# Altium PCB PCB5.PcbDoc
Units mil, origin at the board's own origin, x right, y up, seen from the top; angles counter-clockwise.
Board outline 6000 x 4000 mil, 2 copper layers (Top Layer, Bottom Layer); 73 components, 49 nets, 211 pads, 62 vias.
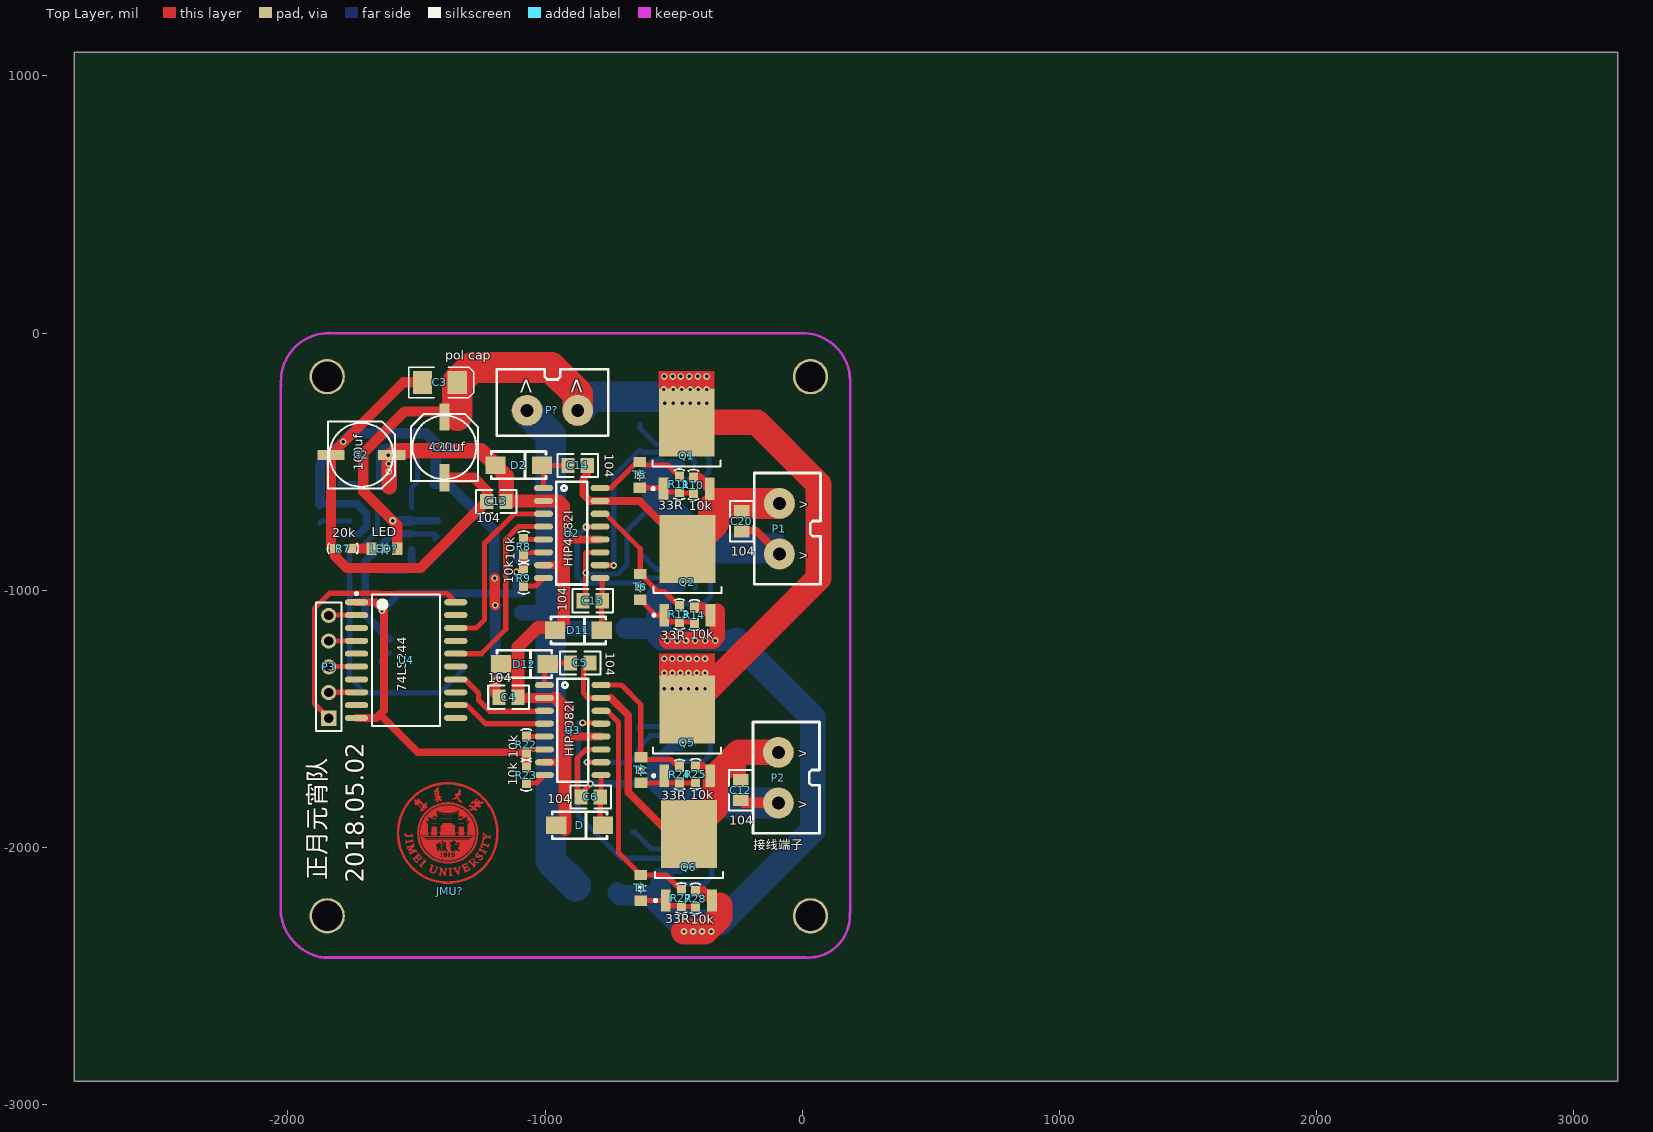
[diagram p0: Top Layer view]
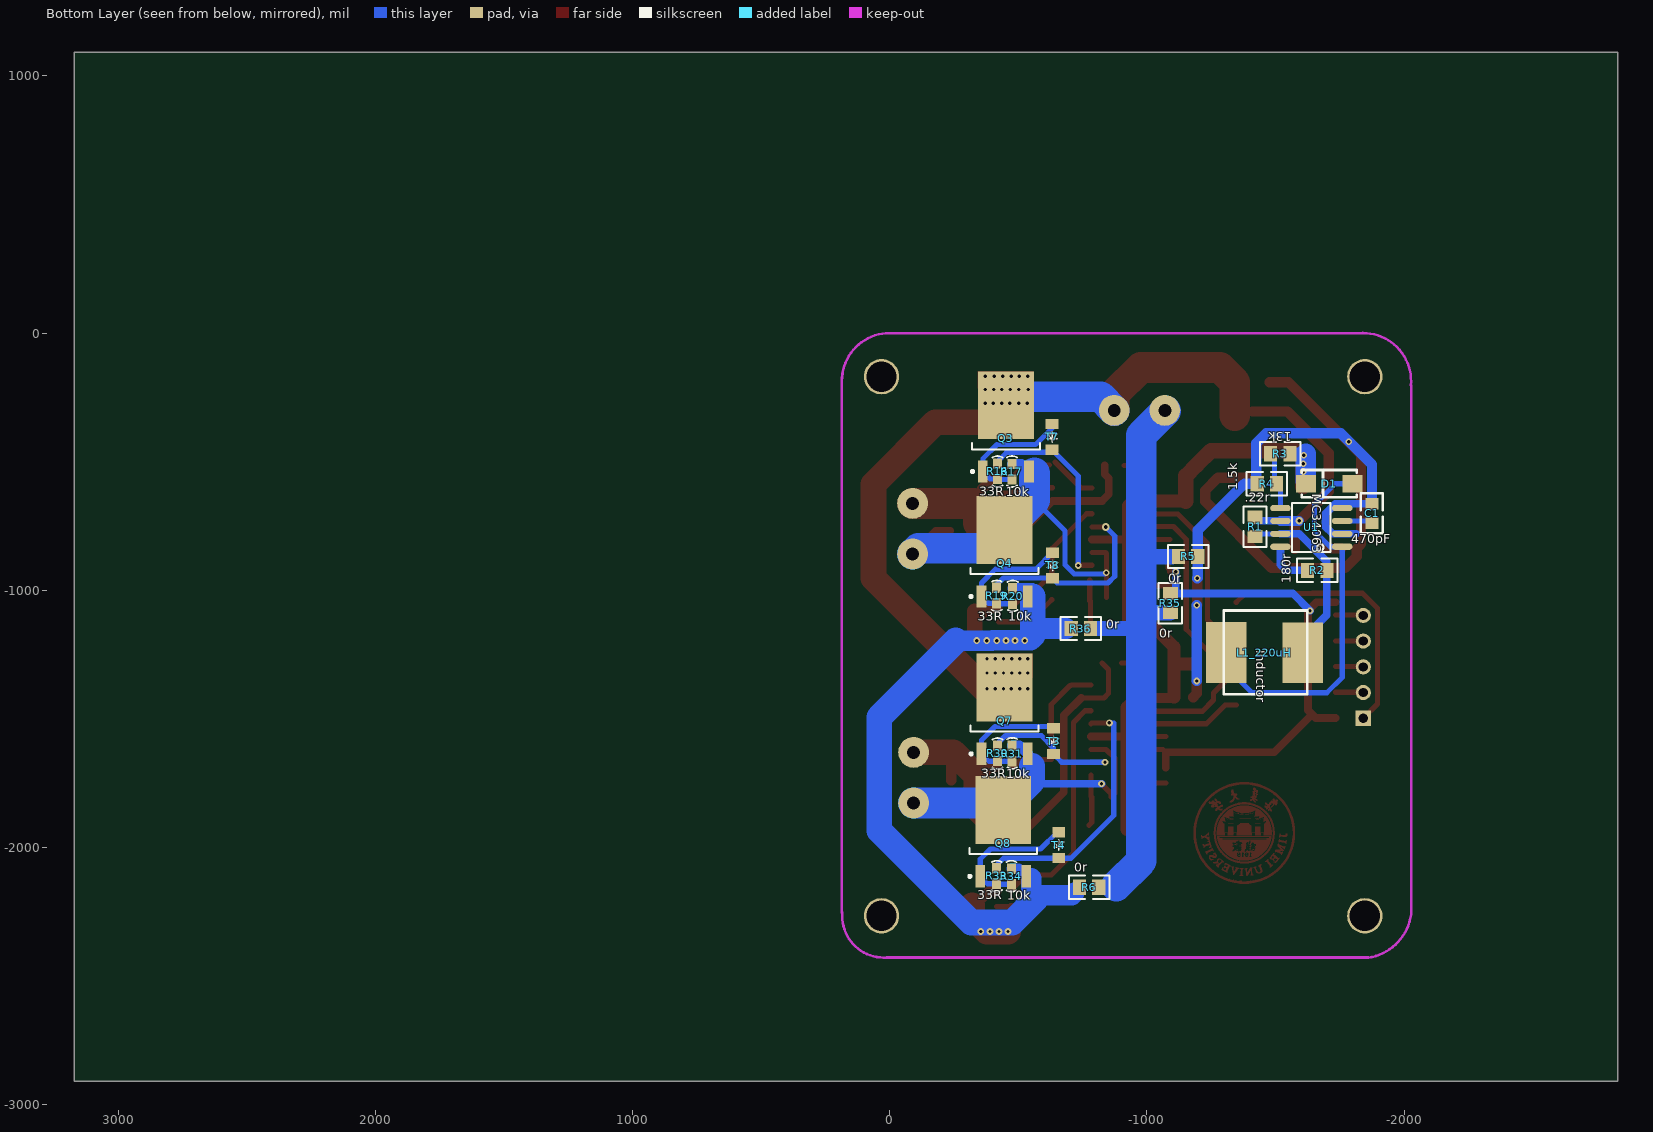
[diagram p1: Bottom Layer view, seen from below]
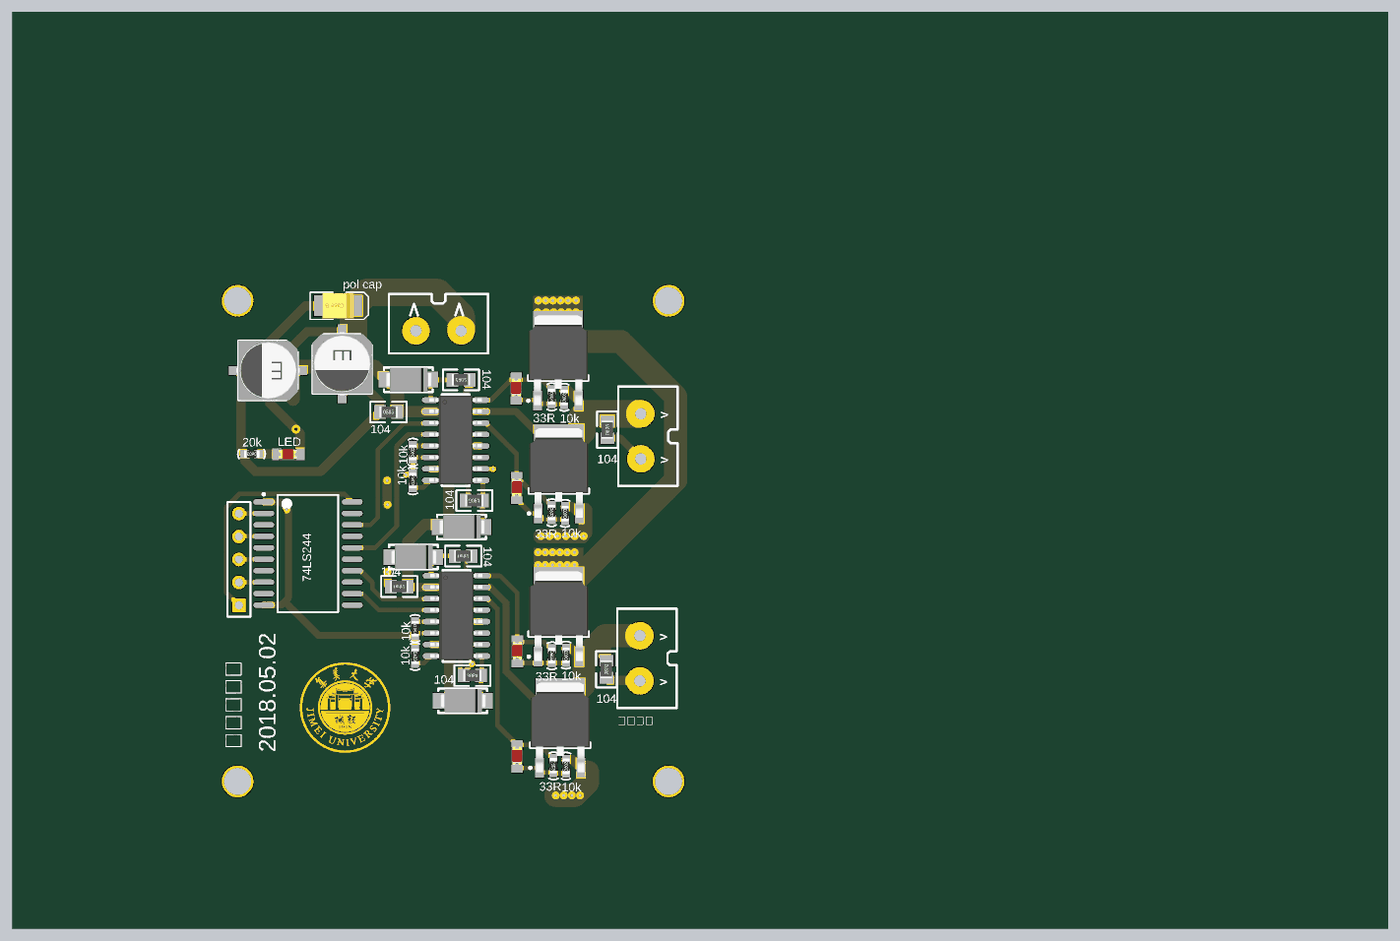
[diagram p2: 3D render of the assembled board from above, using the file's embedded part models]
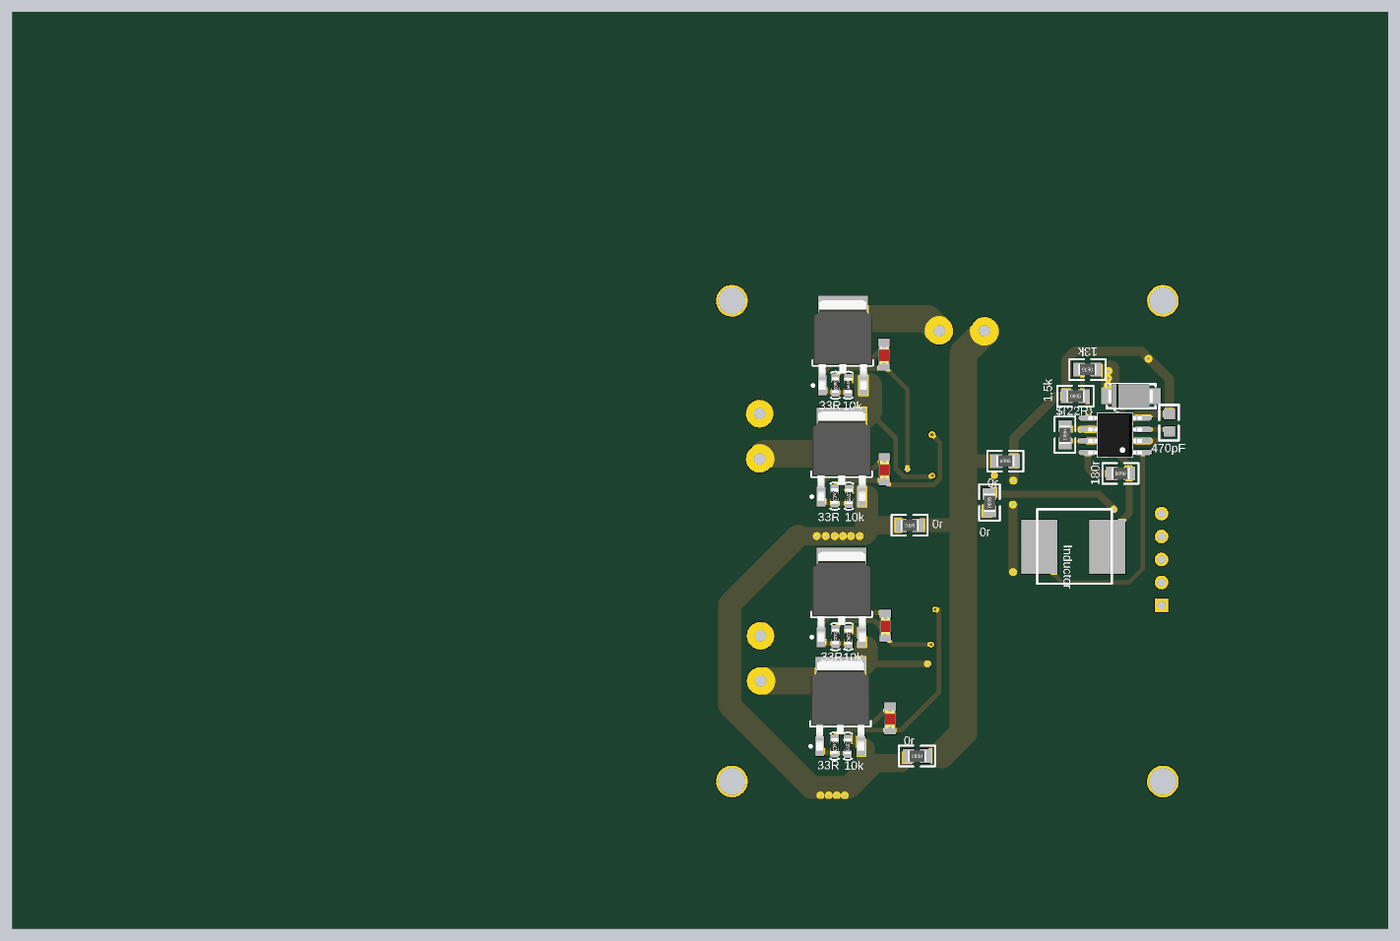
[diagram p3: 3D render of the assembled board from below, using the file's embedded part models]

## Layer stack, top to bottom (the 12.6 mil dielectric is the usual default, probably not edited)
Top Solder: solder mask 0.4, Solder Resist, Dk 3.5
Top Layer: signal copper 1.4
Dielectric 1: dielectric 12.6, FR-4, Dk 4.8
Bottom Layer: signal copper 1.4
Bottom Solder: solder mask 0.4, Solder Resist, Dk 3.5

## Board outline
-2830,-2908 3170,-2908 3170,1092 -2830,1092

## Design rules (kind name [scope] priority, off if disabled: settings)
Clearance [All] p1: gap=10
PolygonConnect [All] p1: connectstyle=Relief reliefconductorwidth=10 reliefentries=4 polygonreliefangle="90 Angle" airgapwidth=10
RoutingVias [All] p1: holewidth=28 width=50 viastyle="Through Hole" minholewidth=28 minwidth=50 maxholewidth=28 maxwidth=50
SolderMaskExpansion [All] p1: expansion=4
Width [All] p1: maxlimit=150 minlimit=10 preferedwidth=20 minimp=50.000000 maximp=50.000000 favimp=50.000000
30 further rules are at their usual default settings.

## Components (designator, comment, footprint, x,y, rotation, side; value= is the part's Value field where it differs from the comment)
C1 "470pF" 0805#1 -1875,-738 r90 bottom
C2 "100uf" ED6.3 -1714,-473 r180 top
C3 "pol cap" "pol cap(10uF)" -1529,-121 r0 top
C4 "104" 0805#2 -1142,-1410 r0 top
C5 "104" 0805#2 -863,-1277 r0 top
C6 "104" 0805#2 -823,-1808 r180 top
C11 "470uf" ED6.3 -1391,-444 r270 top
C12 "104" 0805#2 -244,-1776 r90 top
C13 "104" 0805#2 -1189,-649 r0 top
C14 "104" 0805#2 -873,-509 r0 top
C15 "104" 0805#2 -815,-1045 r180 top
C20 "104" 0805#2 -240,-731 r90 top
D "二极管" 二极管 -861,-1913 r0 top
D1 "二极管" 二极管 -1704,-585 r0 bottom
D2 "D" 二极管 -1098,-513 r0 top
D11 "二极管" 二极管 -866,-1155 r0 top
D12 "二极管" 二极管 -1076,-1286 r0 top
JMU? "LOGO(JMU)" JMU_logo（1） -1369,-2170 r0 top
L1_220uH "Inductor" 电感8*8 -1605,-1242 r270 bottom
LED? "LED" LED(0805) -1625,-838 r180 top
P1 "接线端子" 接线端子 -194,-980 r90 top
P2 "接线端子" 接线端子 -198,-1948 r90 top
P3 "Header 5" HDR1X5 -1841,-1497 r90 top
P? "电源接线端子" 接线端子 -751,-405 r180 top
Q1 "IR7843" "TO-252  mos管" -449.49,-431.19 r90 top
Q2 "IR7843" "TO-252  mos管" -446.49,-923.19 r90 top
Q3 "IR7843" "TO-252  mos管" -451.76,-364.77 r90 bottom
Q4 "IR7843" "TO-252  mos管" -446.49,-850.19 r90 bottom
Q5 "IR7843" "TO-252  mos管" -447.49,-1547.19 r90 top
Q6 "IR7843" "TO-252  mos管" -440.49,-2032.19 r90 top
Q7 "IR7843" "TO-252  mos管" -446.49,-1462.19 r90 bottom
Q8 "IR7843" "TO-252  mos管" -441.49,-1938.19 r90 bottom
R1 ".22r" 0805#2 -1425,-753 r270 bottom
R2 "180r" 0805#2 -1662,-927 r0 bottom
R3 "13k" 0805#2 -1518,-474 r0 bottom
R4 "1.5k" 0805#2 -1466,-580 r180 bottom
R5 "0r" 0805#2 -1160,-863 r180 bottom
R6 "0r" 0805#2 -775,-2159 r0 bottom
R7 "20k" 0603 -1780,-837 r180 top
R8 "10k" 0603 -1083,-835 r90 top
R9 "10k" 0603 -1083,-948 r270 top
R10 "10k" 0603 -423,-596 r90 top
R11 "33R" 0603 -478,-582 r270 top
R13 "33R" 0603 -478,-1087 r270 top
R14 "10k" 0603 -419,-1102 r90 top
R16 "33R" 0603 -419.28,-531.58 r270 bottom
R17 "10k" 0603 -475.28,-543.58 r90 bottom
R19 "33R" 0603 -416,-1015 r270 bottom
R20 "10k" 0603 -478,-1027 r90 bottom
R22 "10k" 0603 -1073,-1604 r90 top
R23 "10k" 0603 -1073,-1714 r270 top
R24 "33R" 0603 -477,-1711 r270 top
R25 "10k" 0603 -415,-1720 r90 top
R27 "33R" 0603 -470,-2191 r270 top
R28 "10k" 0603 -415,-2204 r90 top
R30 "33R" 0603 -419,-1628 r270 bottom
R31 "10k" 0603 -476,-1639 r90 bottom
R33 "33R" 0603 -416,-2105 r270 bottom
R34 "10k" 0603 -473,-2117 r90 bottom
R35 "0r" 0805#2 -1086,-1049 r90 bottom
R36 "0r" 0805#2 -743,-1153 r0 bottom
T1 "二极管" LED(0805) -628,-2156 r90 top
T2 "二极管" LED(0805) -627,-1698 r90 top
T3 "二极管" LED(0805) -637,-1586 r270 bottom
T4 "二极管" LED(0805) -657,-1990 r270 bottom
T5 "二极管" LED(0805) -632,-551 r90 top
T6 "二极管" LED(0805) -630,-986 r90 top
T7 "二极管" LED(0805) -631,-403 r270 bottom
T8 "二极管" LED(0805) -633,-903 r270 bottom
U1 "MC34063" SO8NB -1639,-755 r90 bottom
U2 "HIP4082I" HIP4082I -896,-762 r0 top
U3 "HIP4082I" HIP4082I -892.47,-1528 r0 top
U4 "74LS244" 74LS244D -1540,-1271 r0 top

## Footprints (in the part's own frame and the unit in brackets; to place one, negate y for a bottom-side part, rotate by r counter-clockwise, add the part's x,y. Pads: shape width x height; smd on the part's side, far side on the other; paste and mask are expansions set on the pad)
74LS244D [mm] "SOP-20"
  oval 2.3x0.6 smd: 1(-4.9,5.715) 2(-4.9,4.445) 3(-4.9,3.175) 4(-4.9,1.905) 5(-4.9,0.635) 6(-4.9,-0.635) 7(-4.9,-1.905) 8(-4.9,-3.175) 9(-4.9,-4.445) 10(-4.9,-5.715) 11(4.9,-5.715) 12(4.9,-4.445) 13(4.9,-3.175) 14(4.9,-1.905) 15(4.9,-0.635) 16(4.9,0.635) 17(4.9,1.905) 18(4.9,3.175) 19(4.9,4.445) 20(4.9,5.715)
  silkscreen extent -5.02,-6.5 3.35,6.69, body extent -3.8,-6.5 3.8,6.5, height 2.65
0603 [mil]
  rect 40x35 smd: 1(-25,0) 2(35,0)
  silkscreen extent -54,-20 66,20, body extent -28,-16 38,16, height 22
0805#1 [mil]
  rect 45x50 smd: 1(0,0) 2(75,0)
  silkscreen extent -40,-41 115,44
0805#2 [mil]
  rect 51.18x59.06 smd: 1(-37.4,-5) 2(37.4,-5)
  silkscreen extent -79,-50 79,40, body extent -39,-30 39,20, height 22
ED6.3 [mm]
  rect 2.7x1 smd: 1(-3,0) 2(3,0)
  silkscreen extent -3.3,-3.3 3.3,3.3, body extent -3.5,-3.3 3.5,3.3, height 5.2
HDR1X5 [mm] "Connector; Header; 5 Position"
  rect 1.5x1.5 hole 0.9: 1(0,0)
  round 1.5 hole 0.9: 2(2.54,0) 3(5.08,0) 4(7.62,0) 5(10.16,0)
  silkscreen extent -1.27,-1.27 11.43,1.27
HIP4082I [mil]
  oval 74x24 smd: 1(-110,160) 2(-110,110) 3(-110,60) 4(-110,10) 5(-110,-40) 6(-110,-90) 7(-110,-140) 8(-110,-190) 9(110,-190) 10(110,-140) 11(110,-90) 12(110,-40) 13(110,10) 14(110,60) 15(110,110) 16(110,160)
  silkscreen extent -60,-215 60,185, body extent -115,-207 113,179, height 69
JMU_logo（1） [mil]
  Top Layer region: 8.21,175.64 7.21,175.64 7.21,176.64 8.21,176.64
  Top Layer region: 27.21,181.64 26.21,181.64 26.21,180.64 24.21,180.64 24.21,183.64 27.21,183.64
  Top Layer region: -42.79,162.64 -43.79,162.64 -43.79,161.64 -46.79,161.64 -46.79,163.64 -44.79,163.64 -44.79,164.64 -42.79,164.64
  Top Layer region: -32.79,175.64 -31.79,175.64 -31.79,174.64 -30.79,174.64 -30.79,173.64 -31.79,173.64 -31.79,172.64 -32.79,172.64 -32.79,171.64 -33.79,171.64 -33.79,176.64 -32.79,176.64
  Top Layer region: -29.79,165.64 -30.79,165.64 -30.79,164.64 -31.79,164.64 -31.79,163.64 -33.79,163.64 -33.79,164.64 -34.79,164.64 -34.79,166.64 -31.79,166.64 -31.79,167.64 -29.79,167.64
  Top Layer region: -103.79,318.64 -101.79,318.64 -101.79,313.64 -102.79,313.64 -102.79,312.64 -104.79,312.64 -104.79,313.64 -105.79,313.64 -105.79,314.64 -106.79,314.64 -106.79,319.64 -103.79,319.64
  Top Layer region: -89.79,330.64 -88.79,330.64 -88.79,329.64 -89.79,329.64 -89.79,327.64 -90.79,327.64 -90.79,326.64 -92.79,326.64 -92.79,325.64 -93.79,325.64 -93.79,324.64 -95.79,324.64 -95.79,325.64 -94.79,325.64 -94.79,327.64 -95.79,327.64 -95.79,326.64 -97.79,326.64 -97.79,328.64 -96.79,328.64 -96.79,329.64 -95.79,329.64 -95.79,330.64 -94.79,330.64 -94.79,331.64 -92.79,331.64 -92.79,332.64 -89.79,332.64
  Top Layer region: -40.79,358.64 -37.79,358.64 -37.79,357.64 -34.79,357.64 -34.79,356.64 -32.79,356.64 -32.79,355.64 -31.79,355.64 -31.79,352.64 -32.79,352.64 -32.79,351.64 -36.79,351.64 -36.79,352.64 -37.79,352.64 -37.79,354.64 -39.79,354.64 -39.79,355.64 -41.79,355.64 -41.79,356.64 -42.79,356.64 -42.79,358.64 -41.79,358.64 -41.79,359.64 -40.79,359.64
  Top Layer region: 105.21,357.64 106.21,357.64 106.21,355.64 105.21,355.64 105.21,354.64 104.21,354.64 104.21,353.64 103.21,353.64 103.21,351.64 102.21,351.64 102.21,350.64 101.21,350.64 101.21,349.64 99.21,349.64 99.21,348.64 97.21,348.64 97.21,349.64 96.21,349.64 96.21,352.64 97.21,352.64 97.21,354.64 98.21,354.64 98.21,355.64 99.21,355.64 99.21,356.64 100.21,356.64 100.21,357.64 101.21,357.64 101.21,359.64 105.21,359.64
  Top Layer region: 7.21,87.64 4.21,87.64 4.21,86.64 3.21,86.64 3.21,78.64 4.21,78.64 4.21,64.64 5.21,64.64 5.21,62.64 9.21,62.64 9.21,61.64 8.21,61.64 8.21,60.64 -4.79,60.64 -4.79,61.64 -3.79,61.64 -3.79,62.64 -0.79,62.64 -0.79,72.64 -1.79,72.64 -1.79,86.64 -3.79,86.64 -3.79,87.64 -5.79,87.64 -5.79,89.64 7.21,89.64
  Top Layer region: -100.79,123.64 -99.79,123.64 -99.79,122.64 -98.79,122.64 -98.79,121.64 -97.79,121.64 -97.79,120.64 -96.79,120.64 -96.79,119.64 -94.79,119.64 -94.79,118.64 -93.79,118.64 -93.79,117.64 -92.79,117.64 -92.79,116.64 -91.79,116.64 -91.79,114.64 -93.79,114.64 -93.79,115.64 -96.79,115.64 -96.79,114.64 -97.79,114.64 -97.79,113.64 -98.79,113.64 -98.79,112.64 -99.79,112.64 -99.79,111.64 -100.79,111.64 -100.79,109.64 -101.79,109.64 -101.79,108.64 -102.79,108.64 -102.79,107.64 -103.79,107.64 -103.79,106.64 -104.79,106.64 -104.79,105.64 -105.79,105.64 -105.79,103.64 -106.79,103.64 -106.79,102.64 -107.79,102.64 -107.79,101.64 -108.79,101.64 -108.79,100.64 -109.79,100.64 -109.79,98.64 -110.79,98.64 -110.79,96.64 -109.79,96.64 -109.79,95.64 -108.79,95.64 -108.79,94.64 -109.79,94.64 -109.79,93.64 -110.79,93.64 -110.79,94.64 -111.79,94.64 -111.79,95.64 -112.79,95.64 -112.79,96.64 -113.79,96.64 -113.79,97.64 -115.79,97.64 -115.79,98.64 -116.79,98.64 -116.79,99.64 -117.79,99.64 -117.79,100.64 -118.79,100.64 -118.79,101.64 -119.79,101.64 -119.79,102.64 -116.79,102.64 -116.79,101.64 -114.79,101.64 -114.79,102.64 -113.79,102.64 -113.79,103.64 -112.79,103.64 -112.79,104.64 -111.79,104.64 -111.79,106.64 -110.79,106.64 -110.79,107.64 -109.79,107.64 -109.79,108.64 -108.79,108.64 -108.79,109.64 -107.79,109.64 -107.79,111.64 -106.79,111.64 -106.79,112.64 -105.79,112.64 -105.79,113.64 -104.79,113.64 -104.79,114.64 -103.79,114.64 -103.79,115.64 -102.79,115.64 -102.79,117.64 -101.79,117.64 -101.79,118.64 -100.79,118.64 -100.79,121.64 -101.79,121.64 -101.79,122.64 -102.79,122.64 -102.79,123.64 -101.79,123.64 -101.79,124.64 -100.79,124.64
  Top Layer region: -144.79,199.64 -143.79,199.64 -143.79,194.64 -142.79,194.64 -142.79,190.64 -144.79,190.64 -144.79,192.64 -145.79,192.64 -145.79,193.64 -150.79,193.64 -150.79,192.64 -155.79,192.64 -155.79,191.64 -160.79,191.64 -160.79,190.64 -165.79,190.64 -165.79,189.64 -168.79,189.64 -168.79,188.64 -169.79,188.64 -169.79,184.64 -170.79,184.64 -170.79,185.64 -171.79,185.64 -171.79,190.64 -172.79,190.64 -172.79,195.64 -173.79,195.64 -173.79,197.64 -172.79,197.64 -172.79,198.64 -171.79,198.64 -171.79,196.64 -170.79,196.64 -170.79,195.64 -169.79,195.64 -169.79,194.64 -168.79,194.64 -168.79,195.64 -162.79,195.64 -162.79,196.64 -158.79,196.64 -158.79,197.64 -152.79,197.64 -152.79,198.64 -148.79,198.64 -148.79,199.64 -146.79,199.64 -146.79,203.64 -144.79,203.64
  Top Layer region: 117.21,168.64 118.21,168.64 118.21,167.64 117.21,167.64 117.21,164.64 118.21,164.64 118.21,163.64 120.21,163.64 120.21,162.64 122.21,162.64 122.21,161.64 124.21,161.64 124.21,160.64 126.21,160.64 126.21,159.64 128.21,159.64 128.21,158.64 130.21,158.64 130.21,157.64 132.21,157.64 132.21,156.64 134.21,156.64 134.21,155.64 136.21,155.64 136.21,154.64 139.21,154.64 139.21,155.64 140.21,155.64 140.21,156.64 142.21,156.64 142.21,155.64 141.21,155.64 141.21,153.64 140.21,153.64 140.21,150.64 139.21,150.64 139.21,148.64 138.21,148.64 138.21,146.64 137.21,146.64 137.21,144.64 135.21,144.64 135.21,149.64 134.21,149.64 134.21,150.64 132.21,150.64 132.21,151.64 129.21,151.64 129.21,152.64 128.21,152.64 128.21,153.64 126.21,153.64 126.21,154.64 124.21,154.64 124.21,155.64 122.21,155.64 122.21,156.64 120.21,156.64 120.21,157.64 118.21,157.64 118.21,158.64 116.21,158.64 116.21,159.64 114.21,159.64 114.21,158.64 113.21,158.64 113.21,157.64 112.21,157.64 112.21,156.64 111.21,156.64 111.21,157.64 110.21,157.64 110.21,158.64 111.21,158.64 111.21,160.64 112.21,160.64 112.21,162.64 113.21,162.64 113.21,164.64 114.21,164.64 114.21,166.64 115.21,166.64 115.21,168.64 116.21,168.64 116.21,169.64 117.21,169.64
  Top Layer region: -170.79,223.64 -169.79,223.64 -169.79,221.64 -170.79,221.64 -170.79,220.64 -171.79,220.64 -171.79,219.64 -173.79,219.64 -173.79,217.64 -162.79,217.64 -162.79,218.64 -150.79,218.64 -150.79,219.64 -148.79,219.64 -148.79,223.64 -146.79,223.64 -146.79,216.64 -145.79,216.64 -145.79,210.64 -146.79,210.64 -146.79,209.64 -147.79,209.64 -147.79,212.64 -148.79,212.64 -148.79,213.64 -158.79,213.64 -158.79,212.64 -172.79,212.64 -172.79,213.64 -173.79,213.64 -173.79,214.64 -174.79,214.64 -174.79,215.64 -175.79,215.64 -175.79,217.64 -176.79,217.64 -176.79,221.64 -175.79,221.64 -175.79,223.64 -174.79,223.64 -174.79,224.64 -170.79,224.64
  Top Layer region: 128.21,195.64 131.21,195.64 131.21,194.64 133.21,194.64 133.21,192.64 127.21,192.64 127.21,190.64 126.21,190.64 126.21,188.64 125.21,188.64 125.21,186.64 126.21,186.64 126.21,185.64 129.21,185.64 129.21,184.64 132.21,184.64 132.21,183.64 136.21,183.64 136.21,182.64 139.21,182.64 139.21,181.64 142.21,181.64 142.21,180.64 145.21,180.64 145.21,179.64 148.21,179.64 148.21,180.64 149.21,180.64 149.21,182.64 151.21,182.64 151.21,179.64 150.21,179.64 150.21,176.64 149.21,176.64 149.21,172.64 148.21,172.64 148.21,169.64 146.21,169.64 146.21,173.64 145.21,173.64 145.21,174.64 143.21,174.64 143.21,175.64 140.21,175.64 140.21,176.64 137.21,176.64 137.21,177.64 134.21,177.64 134.21,178.64 130.21,178.64 130.21,179.64 127.21,179.64 127.21,180.64 124.21,180.64 124.21,181.64 123.21,181.64 123.21,178.64 122.21,178.64 122.21,174.64 123.21,174.64 123.21,172.64 125.21,172.64 125.21,171.64 126.21,171.64 126.21,170.64 122.21,170.64 122.21,171.64 119.21,171.64 119.21,172.64 118.21,172.64 118.21,174.64 119.21,174.64 119.21,178.64 120.21,178.64 120.21,181.64 121.21,181.64 121.21,184.64 122.21,184.64 122.21,187.64 123.21,187.64 123.21,190.64 124.21,190.64 124.21,194.64 125.21,194.64 125.21,196.64 128.21,196.64
  Top Layer region: 40.21,95.64 39.21,95.64 39.21,94.64 38.21,94.64 38.21,90.64 37.21,90.64 37.21,84.64 36.21,84.64 36.21,78.64 35.21,78.64 35.21,73.64 34.21,73.64 34.21,72.64 35.21,72.64 35.21,71.64 34.21,71.64 34.21,66.64 33.21,66.64 33.21,64.64 32.21,64.64 32.21,65.64 31.21,65.64 31.21,66.64 30.21,66.64 30.21,67.64 29.21,67.64 29.21,68.64 28.21,68.64 28.21,70.64 27.21,70.64 27.21,71.64 26.21,71.64 26.21,72.64 25.21,72.64 25.21,74.64 24.21,74.64 24.21,75.64 23.21,75.64 23.21,76.64 22.21,76.64 22.21,78.64 21.21,78.64 21.21,79.64 20.21,79.64 20.21,81.64 19.21,81.64 19.21,82.64 18.21,82.64 18.21,83.64 17.21,83.64 17.21,85.64 16.21,85.64 16.21,86.64 15.21,86.64 15.21,87.64 14.21,87.64 14.21,88.64 11.21,88.64 11.21,90.64 14.21,90.64 14.21,91.64 18.21,91.64 18.21,92.64 22.21,92.64 22.21,93.64 23.21,93.64 23.21,90.64 20.21,90.64 20.21,89.64 21.21,89.64 21.21,87.64 22.21,87.64 22.21,85.64 23.21,85.64 23.21,84.64 24.21,84.64 24.21,83.64 25.21,83.64 25.21,81.64 26.21,81.64 26.21,80.64 27.21,80.64 27.21,79.64 28.21,79.64 28.21,77.64 29.21,77.64 29.21,76.64 30.21,76.64 30.21,75.64 31.21,75.64 31.21,74.64 32.21,74.64 32.21,79.64 33.21,79.64 33.21,84.64 34.21,84.64 34.21,91.64 35.21,91.64 35.21,93.64 31.21,93.64 31.21,95.64 34.21,95.64 34.21,96.64 39.21,96.64 39.21,97.64 40.21,97.64
  Top Layer region: 106.21,148.64 108.21,148.64 108.21,147.64 110.21,147.64 110.21,146.64 112.21,146.64 112.21,144.64 104.21,144.64 104.21,143.64 103.21,143.64 103.21,142.64 102.21,142.64 102.21,141.64 101.21,141.64 101.21,138.64 102.21,138.64 102.21,137.64 103.21,137.64 103.21,136.64 108.21,136.64 108.21,137.64 110.21,137.64 110.21,138.64 112.21,138.64 112.21,139.64 115.21,139.64 115.21,140.64 123.21,140.64 123.21,139.64 124.21,139.64 124.21,138.64 125.21,138.64 125.21,137.64 126.21,137.64 126.21,136.64 127.21,136.64 127.21,128.64 126.21,128.64 126.21,127.64 125.21,127.64 125.21,125.64 124.21,125.64 124.21,124.64 123.21,124.64 123.21,123.64 121.21,123.64 121.21,120.64 119.21,120.64 119.21,121.64 117.21,121.64 117.21,122.64 115.21,122.64 115.21,123.64 112.21,123.64 112.21,125.64 120.21,125.64 120.21,126.64 122.21,126.64 122.21,127.64 123.21,127.64 123.21,128.64 124.21,128.64 124.21,132.64 123.21,132.64 123.21,134.64 120.21,134.64 120.21,135.64 118.21,135.64 118.21,134.64 115.21,134.64 115.21,133.64 113.21,133.64 113.21,132.64 111.21,132.64 111.21,131.64 107.21,131.64 107.21,130.64 105.21,130.64 105.21,131.64 102.21,131.64 102.21,132.64 101.21,132.64 101.21,133.64 100.21,133.64 100.21,134.64 99.21,134.64 99.21,136.64 98.21,136.64 98.21,140.64 99.21,140.64 99.21,142.64 100.21,142.64 100.21,144.64 101.21,144.64 101.21,145.64 102.21,145.64 102.21,146.64 104.21,146.64 104.21,149.64 106.21,149.64
  Top Layer region: 130.21,227.64 131.21,227.64 131.21,224.64 132.21,224.64 132.21,223.64 134.21,223.64 134.21,222.64 135.21,222.64 135.21,221.64 136.21,221.64 136.21,220.64 137.21,220.64 137.21,219.64 139.21,219.64 139.21,218.64 140.21,218.64 140.21,217.64 141.21,217.64 141.21,216.64 142.21,216.64 142.21,215.64 144.21,215.64 144.21,214.64 152.21,214.64 152.21,213.64 154.21,213.64 154.21,214.64 155.21,214.64 155.21,217.64 157.21,217.64 157.21,212.64 156.21,212.64 156.21,204.64 154.21,204.64 154.21,207.64 153.21,207.64 153.21,208.64 148.21,208.64 148.21,209.64 143.21,209.64 143.21,208.64 141.21,208.64 141.21,207.64 139.21,207.64 139.21,206.64 137.21,206.64 137.21,205.64 135.21,205.64 135.21,204.64 134.21,204.64 134.21,203.64 132.21,203.64 132.21,202.64 130.21,202.64 130.21,201.64 129.21,201.64 129.21,200.64 128.21,200.64 128.21,198.64 126.21,198.64 126.21,206.64 127.21,206.64 127.21,211.64 129.21,211.64 129.21,208.64 131.21,208.64 131.21,209.64 133.21,209.64 133.21,210.64 135.21,210.64 135.21,211.64 137.21,211.64 137.21,212.64 139.21,212.64 139.21,213.64 140.21,213.64 140.21,214.64 139.21,214.64 139.21,215.64 138.21,215.64 138.21,216.64 136.21,216.64 136.21,217.64 135.21,217.64 135.21,218.64 134.21,218.64 134.21,219.64 132.21,219.64 132.21,220.64 130.21,220.64 130.21,218.64 128.21,218.64 128.21,224.64 129.21,224.64 129.21,228.64 130.21,228.64
  Top Layer region: -73.79,103.64 -71.79,103.64 -71.79,102.64 -68.79,102.64 -68.79,101.64 -66.79,101.64 -66.79,100.64 -63.79,100.64 -63.79,99.64 -62.79,99.64 -62.79,97.64 -64.79,97.64 -64.79,98.64 -66.79,98.64 -66.79,97.64 -67.79,97.64 -67.79,95.64 -68.79,95.64 -68.79,92.64 -69.79,92.64 -69.79,89.64 -70.79,89.64 -70.79,87.64 -71.79,87.64 -71.79,84.64 -72.79,84.64 -72.79,81.64 -73.79,81.64 -73.79,76.64 -72.79,76.64 -72.79,75.64 -71.79,75.64 -71.79,74.64 -70.79,74.64 -70.79,73.64 -68.79,73.64 -68.79,72.64 -62.79,72.64 -62.79,73.64 -61.79,73.64 -61.79,74.64 -60.79,74.64 -60.79,75.64 -59.79,75.64 -59.79,76.64 -58.79,76.64 -58.79,78.64 -57.79,78.64 -57.79,81.64 -56.79,81.64 -56.79,84.64 -55.79,84.64 -55.79,86.64 -54.79,86.64 -54.79,89.64 -53.79,89.64 -53.79,93.64 -54.79,93.64 -54.79,94.64 -55.79,94.64 -55.79,96.64 -53.79,96.64 -53.79,95.64 -50.79,95.64 -50.79,94.64 -48.79,94.64 -48.79,93.64 -45.79,93.64 -45.79,91.64 -49.79,91.64 -49.79,90.64 -50.79,90.64 -50.79,88.64 -51.79,88.64 -51.79,86.64 -52.79,86.64 -52.79,83.64 -53.79,83.64 -53.79,80.64 -54.79,80.64 -54.79,78.64 -55.79,78.64 -55.79,76.64 -56.79,76.64 -56.79,74.64 -57.79,74.64 -57.79,72.64 -59.79,72.64 -59.79,71.64 -60.79,71.64 -60.79,70.64 -62.79,70.64 -62.79,69.64 -68.79,69.64 -68.79,70.64 -71.79,70.64 -71.79,71.64 -73.79,71.64 -73.79,72.64 -75.79,72.64 -75.79,73.64 -76.79,73.64 -76.79,74.64 -77.79,74.64 -77.79,76.64 -78.79,76.64 -78.79,83.64 -77.79,83.64 -77.79,86.64 -76.79,86.64 -76.79,89.64 -75.79,89.64 -75.79,91.64 -74.79,91.64 -74.79,94.64 -73.79,94.64 -73.79,97.64 -72.79,97.64 -72.79,101.64 -74.79,101.64 -74.79,104.64 -73.79,104.64
  Top Layer region: 215 vertices and 0 holes, not listed, extent -145.79,111.64 -108.79,148.64
  Top Layer region: 177 vertices and 0 holes, not listed, extent 43.21,73.64 78.21,109.64
  Top Layer region: -37.79,91.64 -32.79,91.64 -32.79,90.64 -31.79,90.64 -31.79,88.64 -30.79,88.64 -30.79,86.64 -29.79,86.64 -29.79,85.64 -28.79,85.64 -28.79,83.64 -27.79,83.64 -27.79,82.64 -26.79,82.64 -26.79,80.64 -25.79,80.64 -25.79,78.64 -24.79,78.64 -24.79,77.64 -23.79,77.64 -23.79,75.64 -22.79,75.64 -22.79,73.64 -21.79,73.64 -21.79,72.64 -20.79,72.64 -20.79,70.64 -19.79,70.64 -19.79,78.64 -18.79,78.64 -18.79,87.64 -21.79,87.64 -21.79,89.64 -14.79,89.64 -14.79,88.64 -10.79,88.64 -10.79,87.64 -11.79,87.64 -11.79,86.64 -14.79,86.64 -14.79,84.64 -15.79,84.64 -15.79,78.64 -16.79,78.64 -16.79,70.64 -17.79,70.64 -17.79,62.64 -18.79,62.64 -18.79,60.64 -20.79,60.64 -20.79,62.64 -21.79,62.64 -21.79,63.64 -22.79,63.64 -22.79,65.64 -23.79,65.64 -23.79,66.64 -24.79,66.64 -24.79,68.64 -25.79,68.64 -25.79,70.64 -26.79,70.64 -26.79,71.64 -27.79,71.64 -27.79,73.64 -28.79,73.64 -28.79,74.64 -29.79,74.64 -29.79,76.64 -30.79,76.64 -30.79,78.64 -31.79,78.64 -31.79,80.64 -32.79,80.64 -32.79,81.64 -33.79,81.64 -33.79,83.64 -34.79,83.64 -34.79,79.64 -35.79,79.64 -35.79,71.64 -36.79,71.64 -36.79,64.64 -33.79,64.64 -33.79,62.64 -41.79,62.64 -41.79,63.64 -44.79,63.64 -44.79,64.64 -43.79,64.64 -43.79,65.64 -40.79,65.64 -40.79,66.64 -39.79,66.64 -39.79,71.64 -38.79,71.64 -38.79,79.64 -37.79,79.64 -37.79,86.64 -36.79,86.64 -36.79,87.64 -37.79,87.64 -37.79,89.64 -39.79,89.64 -39.79,90.64 -40.79,90.64 -40.79,92.64 -37.79,92.64
  Top Layer region: 139 vertices and 1 holes, not listed, extent 71.21,93.64 111.21,127.64
  Top Layer region: 195 vertices and 0 holes, not listed, extent -168.79,142.64 -127.79,185.64
  Top Layer region: 155 vertices and 0 holes, not listed, extent 10.21,345.64 47.21,395.64
  Top Layer region: 241 vertices and 4 holes, not listed, extent -60.79,345.64 -33.79,402.64
  Top Layer region: 219 vertices and 1 holes, not listed, extent -138.79,311.64 -91.79,360.64
  Top Layer region: 251 vertices and 0 holes, not listed, extent 75.21,313.64 128.21,352.64
  Top Layer region: 261 vertices and 22 holes, not listed, extent -114.79,120.64 96.21,214.64
  Top Layer region: 309 vertices and 19 holes, not listed, extent -115.79,217.64 97.21,333.64
  Top Layer region: 557 vertices and 1 holes, not listed, extent -127.79,108.64 109.21,345.64
  Top Layer region: 917 vertices and 1 holes, not listed, extent -205.79,30.64 187.21,423.64
LED(0805) [mil]
  rect 40x50 smd: 1(-50,0) 2(50,0)
  silkscreen extent -20,-20 20,20, body extent -37,-24 43,25, height 43
"pol cap(10uF)" [mil]
  rect 75x90 smd: 1(187.5,-70) 2(52.5,-70)
  silkscreen extent -1,-129 252,-11, body extent 51,-125 189,-15, height 75
SO8NB [mil]
  oval 24x80 smd: 1(-75,-120) 2(-25,-120) 3(25,-120) 4(75,-120) 5(75,120) 6(25,120) 7(-25,120) 8(-75,120)
  silkscreen extent -95,-75 95,75, body extent -97,-118 96,118, height 61
"TO-252  mos管" [mm]
  rect 2.2x0.95 smd: 1(-4.4,2.28) 3(-4.4,-2.28)
  rect 6.7x5.5 smd: 2(2.15,0)
  silkscreen extent -4.52,-3.35 -1.6,3.43, body extent -4.9,-3.27 5.04,3.27, height 2.39
二极管 [mm] "SS-14/M7"
  rect 2x1.75 smd: 1(-2.413,0) 2(2.187,0)
  silkscreen extent -2.81,-1.35 2.59,1.35, body extent -2.61,-1.34 2.49,1.33, height 2.12
接线端子 [mil]
  round 120 hole 50: 1(121.57,-105) 2(318.43,-105)
  silkscreen extent 3,-265 437,-7
电感8*8 [mm]
  rect 6x4 smd: 1(0,0) 2(-0.025,-7.544)
  silkscreen extent -4.17,-7.77 4.09,0.48

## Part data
C1: library part Cap, "Capacitor"
C2 C11: library part 固态贴片电容, "ED8:470UF  ED6.3:100UF"
C3: "通用有极电容"
C4 C5 C6 C12 C13 C14 C15 C20: library part Cap, "无极电容"
D2: library part 二极管
JMU?: library part JMU-LOGO
LED?: "发光二极管"
P3: "Header, 5-Pin"
P?: "电源线"
Q1 Q2 Q3 Q4 Q5 Q6 Q7 Q8: library part NMOS-2, "N-Channel Power MOSFET"
R1 R2 R3 R4 R5 R6 R7 R8 R9 R10 R11 R13 R14 R16 R17 R19 R20 R22 R23 R24 R25 R27 R28 R30 R31 R33 R34 R35 R36: library part R

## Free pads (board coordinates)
  round 137.8 hole 118.11: 0(-1847,-2265) 0(-1847,-169) 0(32,-2265) 0(32,-169)

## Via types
v1: diameter 26, hole 13, Top Layer to Bottom Layer, 60 vias
v2: diameter 30, hole 15, Top Layer to Bottom Layer, 2 vias

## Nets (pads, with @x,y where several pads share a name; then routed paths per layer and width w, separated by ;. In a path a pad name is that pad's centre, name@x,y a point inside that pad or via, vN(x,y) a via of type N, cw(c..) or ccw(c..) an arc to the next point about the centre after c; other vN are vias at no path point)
5V: P3.1 U4.20 | length 1038.2
  Top Layer w20: P3.1 -1896,-1442 -1896,-1069 -1838,-1011 -1644.5,-1011 -1643.5,-1012 -1381.09,-1012 U4.20
12V: C2.1 C4.2 C13.2 D1.2 D2.1 D11.1 D12.1 D.1 R3.1 U2.2 U2.7 U2.12 U3.2 U3.7 U3.12 | length 3140.8
  Top Layer w30: U2.7 -927,-902 ; U3.7 -924,-1668 ; -922,-1568 U3.12 ; -913,-802 U2.12
  Top Layer w40: C4.2 -1101.6,-1418 U3.2 -959,-1418
  Top Layer w50: C2.1 C2.1@-1579.89,-457 ; D12.1 -1104.6,-1286 ; C13.2 -1150.6,-653 -946,-653 -927,-672 -927,-902 ; C4.2 -1104.6,-1286 ; -959,-1418 -922,-1455 -922,-1568 -922,-1670 ; -927,-914 -927,-1127 -944,-1144 -1029,-1144 -1104.6,-1219.6 -1104.6,-1286 ; -924,-1668 -922,-1670 ; D.1@-922,-1929 -922,-1670
  Top Layer w60: -1605,-597 -1605,-482.11 C2.1 ; C2.1@-1579.89,-457 -1249,-457 D2.1 -1151.6,-554.4 C13.2
  Bottom Layer w50: v1@-1617.9,-469 R3.1
  Bottom Layer w80: D1.2@-1617.9,-575 v1@-1617.9,-469
  other v1: -1607,-538 -1608,-507 -1610,-475
AGND: C1.2 C2.2 C3.2 C4.1 C11.2 C13.1 R4.1 R5.2 R7.2 U1.2 U1.4 | length 3993.7
  Top Layer w40: C3.2 -1550.11,-191 C2.2 -1832.11,-819.89 R7.2 -1815,-868 -1770,-913 -1485.4,-913 C13.1 -1226.4,-611.6 -1275.89,-562.11 C11.2 C11.2@-1391,-577 ; v1(-1195,-953) -1195,-1056 v1(-1193,-1058) ; v1(-1194,-1352) -1194,-1400.4 C4.1
  Bottom Layer w30: C1.2 -1733,-663 -1694,-702 -1694,-752.4 -1721.6,-780 U1.2 -1813,-780
  Bottom Layer w40: C1.2 -1875,-511 -1753,-389 -1463.05,-389 -1425.01,-427.05 R4.1@-1425.01,-581.41 ; R4.1 -1379,-585 -1197.4,-766.6 R5.2 -1197.4,-950.6 v1(-1195,-953) ; v1@-1193,-1351 v1(-1193,-1058)
  other v1: -1784,-422
DGND: R8.1 R9.1 R22.1 R23.1 R35.2 U2.6 U3.6 U4.1 U4.10 | length 2200.2
  Top Layer w20: v1@-1107,-923 v1(-1112,-928) R9.1@-1088,-928 ; R9.1@-1087.5,-918.5 -1082,-913 -1082,-870 -1090,-862 -1080,-852 U2.6 ; R22.1@-1062,-1618 U3.6
  Top Layer w30: U4.10 -1656,-1496 -1642,-1482 ; U4.1 -1659,-1046 -1626,-1079 -1626,-1466 -1642,-1482 ; R23.1 R22.1 -1495,-1629 -1642,-1482
  Bottom Layer w30: v1(-1634,-1079) -1566.6,-1011.6 R35.2 ; R35.2@-1112,-999.6 v1(-1112,-928)
GND: P?.2 R5.1 R6.1 R35.1 R36.1 | length 2325.6
  Bottom Layer w60: R5.1@-1098,-869 -988,-869 ; R35.1 -957.6,-1086.4 ; -948,-1148 R36.1@-791,-1148
  Bottom Layer w120: P?.2@-1072.01,-302.58 -978,-396.59 -978,-2051 -880.5,-2148.5
NetC1_1: C1.1 U1.3 | length 119.3
  Bottom Layer w20: C1.1 -1867,-730 U1.3
NetC5_1: C5.1 D12.2 U3.1 | length 178.4
  Top Layer w20: U3.1 -1002.47,-1298.58 D12.2 -985.9,-1282 C5.1
NetC5_2: C5.2 C12.2 P2.2 Q5.3 Q6.2 R25.2 U3.15 | length 1665.6
  Top Layer w20: C5.2 -851,-1307.4 -851,-1400 -833,-1418 U3.15 -745,-1418
  Top Layer w30: -745,-1418 -677,-1486 -677,-1784 -513.46,-1947.54 Q6.2
  Top Layer w40: R25.2 -393.14,-1685 Q5.3 ; C12.2 -239,-1637.23
  Top Layer w100: Q6.2 -337.5,-1844.55 -337.5,-1720.42 -246.66,-1629.57 P2.2
NetC6_1: C6.1 D.2 U3.9 | length 200.7
  Top Layer w20: U3.9 -782.47,-1799.88 C6.1 -785.6,-1902.3 D.2
NetC6_2: C6.2 C12.1 P2.1 Q7.3 Q8.2 R31.2 U3.11 | length 1381.3
  Top Layer w20: v1(-823,-1752) -860.4,-1789.4 C6.2 -875,-1788.4 -875,-1652.33 -840.67,-1618 U3.11
  Top Layer w40: C12.1@-227.4,-1825 P2.1@-101,-1825
  Top Layer w50: P2.1@-101,-1825 P2.1@-88,-1838
  Bottom Layer w30: v1(-823,-1752) -567.03,-1752
  Bottom Layer w40: Q7.3 -504.84,-1604 R31.2
  Bottom Layer w100: -553.5,-1682.35 -553.5,-1741.53 Q8.2
  Bottom Layer w120: Q8.2 -414.37,-1826.43 P2.1
NetC14_1: C14.1 D2.2 U2.1 | length 185
  Top Layer w20: D2.2 -1010.9,-514 C14.1 ; U2.1 D2.2@-1006,-518.9
NetC14_2: C14.2 C20.2 P1.2 Q1.3 Q2.2 R10.2 U2.15 | length 1131.2
  Top Layer w30: C14.2 -835.6,-547.6 -851.5,-563.5 -851.5,-626.5 -826,-652 U2.15 -633.03,-652 ; -632.03,-653 Q2.2
  Top Layer w40: R10.2 -403.07,-561 Q1.3
  Top Layer w120: Q2.2 -345.5,-737.55 -345.5,-679 ; -327.08,-661.57 P1.2
NetC15_1: C15.1 D11.2 U2.9 | length 195.6
  Top Layer w20: D11.2 -779.9,-1042.3 C15.1 U2.9@-777.6,-960.4
NetC15_2: C15.2 C20.1 P1.1 Q3.3 Q4.2 R17.2 U2.11 | length 1648.1
  Top Layer w20: C15.2@-843,-1028 -843,-856 -839,-852 U2.11
  Top Layer w30: C20.1 -179.02,-768.4 P1.1
  Bottom Layer w20: v1(-842,-931) -837,-936 -717,-936 -682,-901 -682,-768.48 -562.78,-649.25
  Bottom Layer w30: Q3.3@-549.53,-530 Q3.3@-545.53,-534
  Bottom Layer w40: Q3.3@-545.53,-534 Q3.3 -512.11,-508.58 R17.2
  Bottom Layer w120: -562.78,-543 -562.78,-649.25 Q4.2 -376.03,-836 -111.43,-836 P1.1
NetD1_1: D1.1 L1_220uH.2 U1.1 | length 1443.7
  Bottom Layer w20: D1.1 -1732,-585 -1651,-666 -1651,-770 -1711,-830 U1.1 -1759,-1338 -1699,-1398 -1408,-1398 L1_220uH.2@-1308,-1298
NetL1_220uH_1: L1_220uH.1 R1.2 R2.1 U1.7 | length 730.7
  Bottom Layer w20: L1_220uH.1@-1639.4,-1276.4 L1_220uH.1 ; U1.7 -1430.4,-780 R1.2 R1.2@-1428.6,-799
  Bottom Layer w30: L1_220uH.1@-1605,-1190 -1699.4,-1095.6 R2.1 -1699.4,-887.4 -1592,-780 U1.7
NetLED?_2: LED?.2 R7.1 | length 80.4
  Top Layer w40: R7.1 -1676,-837 LED?.2
NetQ1_1: Q1.1 R10.1 R11.2 T5.1 | length 212.5
  Top Layer w20: T5.1 Q1.1@-542.67,-601 ; Q1.1 -526.67,-617 R11.2 -474,-621 R10.1
NetQ2_1: Q2.1 R13.2 R14.1 T6.1 | length 241.6
  Top Layer w20: T6.1 -569.58,-1096.42 Q2.1 -510.67,-1122 R13.2 R14.1@-424,-1122
NetQ3_1: Q3.1 R16.2 R17.1 T7.1 | length 510.4
  Bottom Layer w20: T7.1 -631,-369.33 -567.33,-433 -417,-433 -362,-488 Q3.1 -390.58,-566.58 R16.2 -421.28,-568.58 R17.1
NetQ4_1: Q4.1 R19.2 R20.1 T8.1 | length 510.5
  Bottom Layer w20: T8.1 -568.57,-917.43 -410.57,-917.43 -356.72,-971.28 Q4.1 -383.31,-1050 R19.2 -418,-1052 R20.1
NetQ5_1: Q5.1 R24.2 R25.1 T2.1 | length 213.2
  Top Layer w20: T2.1 -537.25,-1748 -418,-1748 R25.1
NetQ6_1: Q6.1 R27.2 R28.1 T1.1 | length 222.5
  Top Layer w20: T1.1 -537,-2206 -517,-2226 R27.2 -467,-2229 R28.1
NetQ7_1: Q7.1 R30.2 R31.1 T3.1 | length 489.1
  Bottom Layer w20: T3.1 -630.43,-1529.43 -409.57,-1529.43 -356.72,-1582.28 Q7.1 -385.31,-1664 R31.1
NetQ8_1: Q8.1 R33.2 R34.1 T4.1 | length 549
  Bottom Layer w20: T4.1 -651,-1940 -585.57,-2005.43 -391.57,-2005.43 -351.72,-2045.28 Q8.1 -380.31,-2140 R33.2 -418,-2142 R34.1
NetR2_2: R2.2 U1.8 | length 172.1
  Bottom Layer w30: R2.2 -1542,-922 -1519,-899 U1.8@-1519,-842
NetR3_2: R3.2 R4.2 U1.5 | length 226.9
  Bottom Layer w20: U1.5 -1519,-600.6 R4.2 -1496,-577.6 -1496,-484.4 R3.2
NetR8_2: R8.2 U2.5 | length 84
  Top Layer w20: R8.2@-1090,-802 U2.5
NetR9_2: R9.2 U2.8 | length 98.8
  Top Layer w20: R9.2@-1092,-983 -1037,-983 U2.8
NetR11_1: R11.1 T5.2 U2.16 | length 345.1
  Top Layer w20: U2.16 -744,-602 T5.2@-643,-501 ; T5.2@-620,-513 -595.5,-513 -546.5,-513 -522,-513 R11.1
NetR13_1: R13.1 T6.2 U2.14 | length 514.7
  Top Layer w20: U2.14 -765.75,-702 -630,-837.75 T6.2 -562,-1004 -536,-1004 R13.1
NetR16_1: R16.1 T7.2 U2.10 | length 784.1
  Top Layer w20: U2.10 -734,-902 v1(-733,-903)
  Bottom Layer w20: v1(-733,-903) -733,-555 T7.2 -621,-463 -455.08,-463 -419.28,-498.8 R16.1
NetR19_1: R19.1 T8.2 U2.13 | length 760.3
  Top Layer w20: v2(-840,-753) U2.13@-787,-753
  Bottom Layer w20: v2(-840,-753) -875,-788 -875,-944.67 -848.67,-971 -651,-971 T8.2 -633,-952 -442,-952 -416,-978 R19.1
NetR22_2: R22.2 U3.5 | length 70.5
  Top Layer w20: R22.2@-1073,-1568 U3.5
NetR23_2: R23.2 U3.8 | length 83.4
  Top Layer w20: R23.2 -1033.47,-1749 U3.8
NetR24_1: R24.1 T2.2 U3.16 | length 562.6
  Top Layer w20: U3.16 -706,-1368 -704,-1370 -701,-1370 -628,-1443 -628,-1657.11 -510.27,-1657.11 -481.38,-1686 R24.1
NetR27_1: R27.1 T1.2 U3.14 | length 898.6
  Top Layer w20: U3.14 -759,-1468 -714,-1513 -714,-2020 T1.2 -530,-2106 R27.1
NetR30_1: R30.1 T3.2 U3.10 | length 539.8
  Top Layer w20: v1(-837,-1668) U3.10
  Bottom Layer w20: v1(-837,-1668) -669,-1668 ; -667,-1666 T3.2 -637,-1612 -589,-1564 -450.22,-1564 R30.1@-419,-1595.22
NetR33_1: R33.1 T4.2 U3.13 | length 997.3
  Top Layer w20: v1(-854,-1515) -785.47,-1515 U3.13
  Bottom Layer w20: v1(-854,-1515) -871,-1515 -871,-1875 -705,-2041 -442,-2041 -416,-2067 R33.1
PGND: Q2.3 Q4.3 Q6.3 Q8.3 R6.2 R14.2 R20.2 R28.2 R34.2 R36.2 | length 3255.9
  Top Layer w40: R14.2 -386.14,-1067 Q2.3 ; R28.2 -387.14,-2169 Q6.3
  Top Layer w60: v1@-345,-1195 -331,-1181 -331,-1081
  Top Layer w65: v1(-525,-1195) v1@-345,-1195
  Top Layer w100: v1(-460,-2326) -377,-2326 -321,-2270 -321,-2224
  Bottom Layer w40: Q4.3@-554,-992 R20.2 ; Q8.3 -501.84,-2082 R34.2
  Bottom Layer w80: R6.2@-716.8,-2174.8 -706.6,-2185 -572,-2185 ; R36.2@-686,-1148 -595,-1148 ; -572,-2195 -572,-2185 ; -550.57,-2119 -550.57,-2163.57 -572,-2185 ; -549,-1180 -549,-1194 -401,-1194 ; -396,-1195 -257,-1195
  Bottom Layer w100: -572,-2195 -476,-2291 -317,-2291 41,-1933 41,-1493 -257,-1195 ; -555.5,-1023.42 -555.5,-1173.5 -549,-1180
  other v1: -425,-2326 -390,-2326 -354,-2326 -487,-1195 -452,-1195 -416,-1195 -377,-1195 -338,-1195
PWM1: P3.5 U4.2 | length 108.5
  Top Layer w20: P3.5 -1840,-1096 U4.2
PWM2: P3.4 U4.4 | length 108.5
  Top Layer w20: P3.4 -1840,-1196 U4.4
PWM3: P3.3 U4.6 | length 108.5
  Top Layer w20: P3.3 -1840,-1296 U4.6
PWM4: P3.2 U4.8 | length 108.5
  Top Layer w20: P3.2 -1840,-1396 U4.8
PWMOUT1: U2.3 U4.18 | length 698.4
  Top Layer w20: U4.18 -1267,-1146 -1235,-1114 -1235,-818 -1120.53,-703.53 -1007.53,-703.53 U2.3
PWMOUT2: U2.4 U4.16 | length 750.1
  Top Layer w20: U4.16 -1248,-1246 -1153,-1151 -1153,-802 -1103,-752 U2.4
PWMOUT3: U3.3 U4.14 | length 411.9
  Top Layer w20: U4.14 -1311.56,-1346 -1259,-1398.56 -1259,-1426 -1215.47,-1469.53 U3.3@-1002.47,-1469.53
PWMOUT4: U3.4 U4.12 | length 374.4
  Top Layer w20: U4.12 -1303,-1446 -1231,-1518 U3.4
VCC: C3.1 C11.1 LED?.1 P?.1 Q1.2 Q3.2 Q5.2 Q7.2 R1.1 U1.6 | length 3829.2
  Top Layer w40: LED?.1 -1575,-746 v2(-1592,-729) -1707,-614 -1707,-466 -1545,-304 -1411,-304
  Top Layer w100: Q1.2 -177.46,-346.54 63,-587 63,-952.05 Q5.2
  Top Layer w120: -1341.5,-319.5 C3.1 -1283.5,-133 -976,-133 -872.57,-236.43 P?.1
  Bottom Layer w30: U1.6@-1504,-729 R1.1@-1420,-729
  Bottom Layer w40: v2@-1591,-730 U1.6
  Bottom Layer w120: P?.1 -819.57,-247 -484.89,-247 Q3.2
  other v1: -537,-1382 -505,-1382 -473,-1382 -442,-1382 -410,-1382 -378,-1382 -537,-1321 -506,-1321 -474,-1321 -442,-1321 -410,-1321 -378,-1321 -537,-1266 -506,-1266 -474,-1266 -442,-1266 -410,-1266 -378,-1266 -535,-273 -501,-273 -467,-273 -435,-273 -403,-273 -371,-273 -539,-219 -502,-219 -469,-219 -436,-219 -404,-219 -372,-219 -536,-168 -504,-168 -472,-168 -439,-168 -406,-168 -372,-168
pads on no net: U4.3 U4.5 U4.7 U4.9 U4.11 U4.13 U4.15 U4.17 U4.19

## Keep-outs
Keep-Out Layer:
  lines w10: -2027,-203 -2027,-2260 ccw(c-1831,-2232) -1860.12,-2427.84 ; -2025.92,-202.9 cw(c-1840,-186) -1824,0 0,0 cw(c1,-185) 186,-185 ; -1860,-2427 11,-2427 ccw(c23,-2266) 183.85,-2252.18 ; 186,-2252 186,-186

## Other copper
Top Layer:
  rectangle net VCC: -556,-1340 -339,-1246
  rectangle net VCC: -558,-215 -342,-147

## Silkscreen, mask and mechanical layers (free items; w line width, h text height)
Top Overlay:
  text "正月元宵队" at -1829,-2126 h118.11 r90
  text "2018.05.02" at -1682,-2137 h118.11 r90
